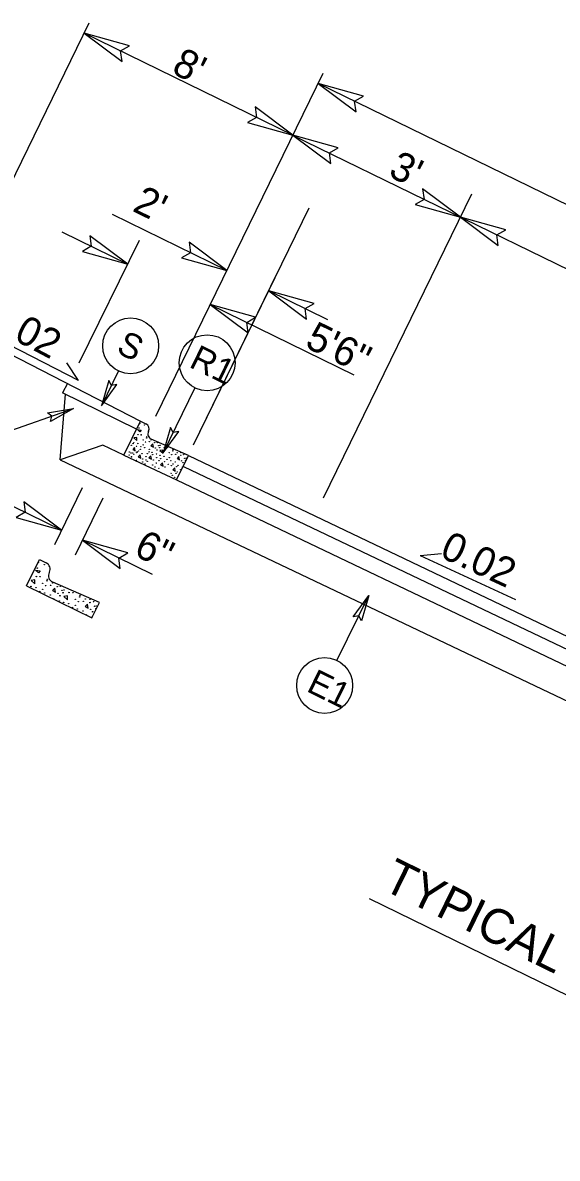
# Model space of a CAD drawing. Extents: x 1518247 to 1523638, y 635234 to 639927.
# Drawn here: x 1522742.5 to 1522926, y 636882.6 to 637272.1 of the extents above; entities that cross this region are included whole.
import ezdxf

# ---------------------------------------------------------------- set-up
doc = ezdxf.new("R2010")
doc.units = 0
for name, color, linetype in [('Prop Dimension', 7, 'Continuous'), ('Prop Dimension Text', 7, 'Continuous'), ('Prop Shade Light', 7, 'Continuous'), ('Typical Arrow Superelevation CELL', 7, 'Continuous'), ('Typical Berm CELL', 7, 'Continuous'), ('Typical Berm Information CELL', 7, 'Continuous'), ('Typical Curb CELL', 7, 'Continuous'), ('Typical Hinge Slope Interstate CELL', 7, 'Continuous'), ('Typical ID Circle CELL', 7, 'Continuous'), ('Typical Pavement Slope CELL', 7, 'Continuous'), ('Typical Pavement Slope Information CELL', 7, 'Continuous'), ('Typical Text ID Circle CELL', 7, 'Continuous'), ('Typical Text Label CELL', 7, 'Continuous')]:
    doc.layers.add(name, color=color, linetype=linetype)

# ---------------------------------------------------------------- blocks, each defined once
blk = doc.blocks.new('TERMINATOR')
at = {"layer": 'Prop Shade Light'}
blk.add_lwpolyline([(-0.469, 0.081), (0, 0), (-0.471, -0.083), (-0.411, 0)], close=True, dxfattribs=at)

msp = doc.modelspace()

# ---------------------------------------------------------------- linework, layer by layer
at = {"layer": 'Prop Dimension'}
for p, q in [((1522717.34, 637173.63), (1522765.38, 637272.05)), ((1522835.27, 637233.49), (1522763.63, 637268.47)), ((1522788.25, 637137.16), (1522845.66, 637254.76)), ((1523261.87, 637047.19), (1522843.93, 637251.22)), ((1523044.19, 637131.41), (1522835.23, 637233.41)), ((1522845.74, 637109.11), (1522896.65, 637213.41)), ((1522801.16, 637127.25), (1522840.88, 637208.62)), ((1522812.62, 637187.09), (1522773.32, 637206.27)), ((1522755.94, 637200.38), (1522778.55, 637189.3)), ((1522761.93, 637155.39), (1522782.56, 637197.49)), ((1522801.16, 637127.26), (1522829.89, 637186.12)), ((1522847.25, 637170.18), (1522826.95, 637180.09)), ((1522806.91, 637175.4), (1522856.1, 637151.3)), ((1522755.85, 637098.06), (1522727.21, 637112.05)), ((1522762.91, 637112.52), (1522753.38, 637093)), ((1522770.07, 637109.03), (1522760.54, 637089.5)), ((1522787.02, 637082.85), (1522763.01, 637094.56))]:
    msp.add_line(p, q, dxfattribs=at)
at = {"layer": 'Prop Shade Light'}
for points in [[(1522772.04, 637149.31), (1522769.52, 637140.66), (1522774.85, 637147.99), (1522772.94, 637147.66)], [(1522751.04, 637138.26), (1522759.92, 637139.77), (1522752.03, 637135.32), (1522752.57, 637137.18)], [(1522793.25, 637133.22), (1522790.73, 637124.58), (1522796.07, 637131.91), (1522794.15, 637131.58)], [(1522855.97, 637068.32), (1522861.25, 637075.62), (1522858.74, 637066.91), (1522857.82, 637068.62)]]:
    msp.add_lwpolyline(points, close=True, dxfattribs=at)
at = {"layer": 'Typical Arrow Superelevation CELL'}
msp.add_line((1522761.64, 637149.3), (1522757.69, 637155.44), dxfattribs=at)
at = {"layer": 'Typical Berm CELL'}
for p, q in [((1522715.59, 637170.05), (1522782.95, 637135.4)), ((1522781.6, 637132.64), (1522756.23, 637145.14))]:
    msp.add_line(p, q, dxfattribs=at)
at = {"layer": 'Typical Berm Information CELL'}
msp.add_line((1522761.64, 637149.3), (1522727.1, 637167.06), dxfattribs=at)
at = {"layer": 'Typical Curb CELL'}
for p, q in [((1522777.24, 637123.7), (1522782.95, 637135.4)), ((1522782.95, 637135.4), (1522784.82, 637134.49)), ((1522781.68, 637129.84), (1522780.68, 637129.66)), ((1522780.68, 637129.66), (1522781.72, 637128.8)), ((1522781.72, 637128.8), (1522781.68, 637129.84)), ((1522782.71, 637131.76), (1522781.89, 637132.57)), ((1522781.89, 637132.57), (1522783.15, 637132.35)), ((1522783.15, 637132.35), (1522782.71, 637131.76)), ((1522785.66, 637131.86), (1522785.7, 637131.94)), ((1522799.41, 637123.67), (1522786.61, 637129.27)), ((1522780.93, 637126.38), (1522780.28, 637125.69)), ((1522780.28, 637125.69), (1522781.13, 637125.22)), ((1522781.13, 637125.22), (1522780.93, 637126.38)), ((1522787.19, 637127.65), (1522786.54, 637126.96)), ((1522786.54, 637126.96), (1522787.38, 637126.49)), ((1522787.38, 637126.49), (1522787.19, 637127.65)), ((1522790.63, 637125.47), (1522789.63, 637125.3)), ((1522789.63, 637125.3), (1522790.67, 637124.43)), ((1522790.67, 637124.43), (1522790.63, 637125.47)), ((1522777.24, 637123.7), (1522795.32, 637115.31)), ((1522782.82, 637123.87), (1522782.18, 637123.18)), ((1522782.18, 637123.18), (1522783.02, 637122.71)), ((1522783.02, 637122.71), (1522782.82, 637123.87)), ((1522786.49, 637123.54), (1522785.85, 637122.85)), ((1522785.85, 637122.85), (1522786.69, 637122.38)), ((1522786.69, 637122.38), (1522786.49, 637123.54)), ((1522790.49, 637121.17), (1522789.85, 637120.48)), ((1522790.69, 637120.01), (1522790.49, 637121.17)), ((1522795.32, 637115.31), (1522799.41, 637123.67)), ((1522796.14, 637123.28), (1522795.49, 637122.59)), ((1522795.49, 637122.59), (1522796.34, 637122.12)), ((1522796.34, 637122.12), (1522796.14, 637123.28)), ((1522789.85, 637120.48), (1522790.69, 637120.01)), ((1522794.7, 637119.41), (1522794.06, 637118.71)), ((1522794.06, 637118.71), (1522794.9, 637118.24)), ((1522794.9, 637118.24), (1522794.7, 637119.41)), ((1522743.84, 637078.94), (1522748.24, 637087.92)), ((1522748.24, 637087.92), (1522750.58, 637086.78)), ((1522747.94, 637083.35), (1522746.9, 637084.37)), ((1522746.9, 637084.37), (1522748.49, 637084.09)), ((1522748.49, 637084.09), (1522747.94, 637083.35)), ((1522751.63, 637083.48), (1522751.68, 637083.57)), ((1522743.84, 637078.94), (1522766.3, 637067.96)), ((1522746.64, 637080.95), (1522745.38, 637080.73)), ((1522745.38, 637080.73), (1522746.69, 637079.65)), ((1522746.69, 637079.65), (1522746.64, 637080.95)), ((1522753.54, 637078.2), (1522752.74, 637077.33)), ((1522768.86, 637073.2), (1522752.82, 637080.23)), ((1522753.79, 637076.75), (1522753.54, 637078.2)), ((1522752.74, 637077.33), (1522753.79, 637076.75)), ((1522757.85, 637075.46), (1522756.6, 637075.24)), ((1522756.6, 637075.24), (1522757.91, 637074.16)), ((1522757.91, 637074.16), (1522757.85, 637075.46)), ((1522764.76, 637072.71), (1522763.95, 637071.84)), ((1522763.95, 637071.84), (1522765.01, 637071.25)), ((1522765.01, 637071.25), (1522764.76, 637072.71)), ((1522766.3, 637067.96), (1522768.86, 637073.2))]:
    msp.add_line(p, q, dxfattribs=at)
for centre, radius in [((1522782.39, 637133.08), 0.064), ((1522782.66, 637134.57), 0.064), ((1522784.34, 637134.05), 0.064), ((1522782.13, 637130.78), 0.064), ((1522783.17, 637130.72), 0.064), ((1522783.86, 637128.93), 0.064), ((1522785.05, 637129.61), 0.064), ((1522785.11, 637130.03), 0.064), ((1522786.58, 637129.01), 0.064), ((1522779.09, 637124.85), 0.064), ((1522779.76, 637127.1), 0.064), ((1522780.33, 637127.73), 0.064), ((1522780.65, 637128.06), 0.064), ((1522781.58, 637126.77), 0.064), ((1522781.78, 637124.9), 0.064), ((1522782.02, 637127.75), 0.064), ((1522782.22, 637125.23), 0.064), ((1522782.91, 637125.77), 0.064), ((1522783.07, 637126.68), 0.064), ((1522783.88, 637127.3), 0.064), ((1522784.39, 637126.28), 0.064), ((1522784.66, 637128.28), 0.064), ((1522785.89, 637124.9), 0.064), ((1522785.95, 637125.73), 0.064), ((1522786.02, 637128.38), 0.064), ((1522787.84, 637128.05), 0.064), ((1522788.04, 637126.18), 0.064), ((1522788.57, 637125.51), 0.064), ((1522788.68, 637128.01), 0.064), ((1522789.17, 637127.04), 0.064), ((1522789.48, 637126.34), 0.064), ((1522789.69, 637127.09), 0.064), ((1522791.08, 637126.41), 0.064), ((1522792.12, 637126.35), 0.064), ((1522794.01, 637125.24), 0.064), ((1522794.06, 637125.66), 0.064), ((1522779.06, 637123.82), 0.064), ((1522779.69, 637124.46), 0.064), ((1522779.86, 637123.18), 0.064), ((1522780.25, 637124.51), 0.064), ((1522780.66, 637124.07), 0.064), ((1522781.58, 637121.95), 0.064), ((1522781.66, 637124.6), 0.064), ((1522783.48, 637124.27), 0.064), ((1522783.65, 637121.38), 0.064), ((1522783.68, 637122.4), 0.064), ((1522784.81, 637123.26), 0.064), ((1522784.84, 637122.06), 0.064), ((1522785.25, 637121.62), 0.064), ((1522785.33, 637124.27), 0.064), ((1522786.85, 637124.68), 0.064), ((1522787.14, 637123.94), 0.064), ((1522787.34, 637122.07), 0.064), ((1522788.33, 637121.02), 0.064), ((1522788.44, 637124.11), 0.064), ((1522788.47, 637122.93), 0.064), ((1522789.33, 637121.9), 0.064), ((1522789.6, 637123.69), 0.064), ((1522789.89, 637122.53), 0.064), ((1522790.97, 637123.38), 0.064), ((1522791.14, 637121.57), 0.064), ((1522792.02, 637122.31), 0.064), ((1522792.81, 637124.56), 0.064), ((1522792.83, 637122.93), 0.064), ((1522793.35, 637121.91), 0.064), ((1522793.61, 637123.91), 0.064), ((1522794.9, 637121.36), 0.064), ((1522794.97, 637124.01), 0.064), ((1522795.53, 637124.64), 0.064), ((1522796.79, 637123.68), 0.064), ((1522796.82, 637124.57), 0.064), ((1522796.99, 637121.81), 0.064), ((1522797.52, 637121.14), 0.064), ((1522797.78, 637123.95), 0.064), ((1522798.12, 637122.67), 0.064), ((1522798.43, 637121.97), 0.064), ((1522798.64, 637122.72), 0.064), ((1522784.45, 637120.73), 0.064), ((1522787.13, 637120.34), 0.064), ((1522787.93, 637119.69), 0.064), ((1522789.25, 637119.25), 0.064), ((1522791.34, 637119.7), 0.064), ((1522792.48, 637120.56), 0.064), ((1522793.46, 637117.48), 0.064), ((1522793.54, 637120.13), 0.064), ((1522794.1, 637120.76), 0.064), ((1522795.1, 637117.51), 0.064), ((1522795.36, 637119.8), 0.064), ((1522795.56, 637117.93), 0.064), ((1522795.8, 637120.31), 0.064), ((1522796.69, 637118.8), 0.064), ((1522797.39, 637119.74), 0.064), ((1522793.9, 637116.83), 0.064), ((1522794.7, 637116.18), 0.064), ((1522747.87, 637086.87), 0.0802), ((1522749.97, 637086.23), 0.0802), ((1522747.21, 637082.13), 0.0802), ((1522747.53, 637085.01), 0.0802), ((1522748.51, 637082.06), 0.0802), ((1522745.35, 637078.72), 0.0802), ((1522747.06, 637078.32), 0.0802), ((1522749.37, 637079.8), 0.0802), ((1522750.37, 637078.99), 0.0802), ((1522750.87, 637080.66), 0.0802), ((1522750.94, 637081.18), 0.0802), ((1522752.08, 637079.11), 0.0802), ((1522752.79, 637079.9), 0.0802), ((1522754.36, 637078.69), 0.0802), ((1522755.47, 637078.75), 0.0802), ((1522748.37, 637076.98), 0.0802), ((1522749.39, 637077.76), 0.0802), ((1522750.04, 637076.49), 0.0802), ((1522751.98, 637075.79), 0.0802), ((1522753.12, 637074.47), 0.0802), ((1522754.61, 637076.35), 0.0802), ((1522755.27, 637075.52), 0.0802), ((1522756.03, 637077.43), 0.0802), ((1522756.41, 637076.55), 0.0802), ((1522756.68, 637077.49), 0.0802), ((1522758.43, 637076.64), 0.0802), ((1522759.73, 637076.57), 0.0802), ((1522760.59, 637074.31), 0.0802), ((1522762.09, 637075.17), 0.0802), ((1522762.16, 637075.7), 0.0802), ((1522764.01, 637074.41), 0.0802), ((1522765.62, 637074.32), 0.0802), ((1522755.11, 637073.75), 0.0802), ((1522756.57, 637073.23), 0.0802), ((1522758.28, 637072.84), 0.0802), ((1522759.59, 637071.5), 0.0802), ((1522760.61, 637072.27), 0.0802), ((1522761.26, 637071), 0.0802), ((1522761.59, 637073.5), 0.0802), ((1522763.21, 637070.3), 0.0802), ((1522763.3, 637073.62), 0.0802), ((1522765.58, 637073.21), 0.0802), ((1522765.83, 637070.86), 0.0802), ((1522766.82, 637073.54), 0.0802), ((1522767.25, 637071.95), 0.0802), ((1522767.63, 637071.06), 0.0802), ((1522767.9, 637072.01), 0.0802), ((1522764.34, 637068.98), 0.0802), ((1522766.33, 637068.26), 0.0802), ((1522766.49, 637070.03), 0.0802)]:
    msp.add_circle(centre, radius, dxfattribs=at)
for centre, radius, start, end in [((1522783.98, 637132.78), 1.91, 333.9793, 63.9793), ((1522787.38, 637131.02), 1.91, 153.9793, 246.3637), ((1522749.52, 637084.63), 2.4, 333.9377, 63.9377), ((1522753.78, 637082.43), 2.4, 153.9377, 246.3222)]:
    msp.add_arc(centre, radius, start, end, dxfattribs=at)
at = {"layer": 'Typical Hinge Slope Interstate CELL'}
msp.add_line((1522757.86, 637148.3), (1522756.23, 637145.14), dxfattribs=at)
at = {"layer": 'Typical ID Circle CELL'}
for p, q in [((1522775.36, 637152.62), (1522769.52, 637140.66)), ((1522801.6, 637146.84), (1522790.73, 637124.58)), ((1522736.55, 637131.53), (1522759.92, 637139.77)), ((1522850.35, 637053.37), (1522861.25, 637075.62))]:
    msp.add_line(p, q, dxfattribs=at)
for centre in [(1522779.56, 637161.23), (1522805.81, 637155.45), (1522846.13, 637044.76)]:
    msp.add_circle(centre, 9.59, dxfattribs=at)
at = {"layer": 'Typical Pavement Slope CELL'}
for p, q in [((1522755.34, 637122.13), (1522757.24, 637144.64)), ((1522770.07, 637127.19), (1522755.34, 637122.13)), ((1522777.24, 637123.7), (1522770.07, 637127.19)), ((1522755.34, 637122.13), (1522986.45, 637012.21)), ((1522799.41, 637123.67), (1522994.84, 637030.3)), ((1522797.66, 637119.84), (1522993.16, 637026.68)), ((1522795.32, 637115.31), (1522990.92, 637021.86))]:
    msp.add_line(p, q, dxfattribs=at)
at = {"layer": 'Typical Pavement Slope Information CELL'}
for q in [(1522886.19, 637090.01), (1522911.58, 637074.21)]:
    msp.add_line((1522878.93, 637089.35), q, dxfattribs=at)
at = {"layer": 'Typical Text Label CELL'}
msp.add_line((1522861.46, 636971.76), (1523043.36, 636882.64), dxfattribs=at)

# ---------------------------------------------------------------- block references
at = {"layer": 'Prop Dimension', "xscale": 33.82820784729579, "yscale": -36.41552511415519}
for p, rotation in [((1522763.63, 637268.47), 153.97926941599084), ((1522843.93, 637251.22), 153.97926941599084), ((1522835.27, 637233.49), -26.020730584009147), ((1522835.27, 637233.49), 153.97926941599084), ((1522892.73, 637205.36), -26.020730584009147), ((1522892.73, 637205.36), 153.97926941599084), ((1522778.55, 637189.3), -26.020730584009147), ((1522812.62, 637187.09), -26.020730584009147), ((1522826.95, 637180.09), 153.97926941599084), ((1522806.91, 637175.4), 153.97926941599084), ((1522755.85, 637098.06), -26.020730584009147), ((1522763.01, 637094.56), 153.97926941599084)]:
    msp.add_blockref('TERMINATOR', p, dxfattribs=dict(at, rotation=rotation))

# ---------------------------------------------------------------- texts
at = {"layer": 'Prop Dimension'}
for s, p in [("8'", (1522793.22, 637254.95)), ("3'", (1522867.58, 637219.59)), ("2'", (1522779.79, 637207.63)), ('5\'6"', (1522838.95, 637161.01)), ('6"', (1522780.21, 637089.62))]:
    msp.add_text(s, height=9.969, rotation=333.9793, dxfattribs=at).set_placement(p)
at = {"layer": 'Prop Dimension Text'}
msp.add_text('TYPICAL SECTION NO. 2', height=11.9625, rotation=333.8962, dxfattribs=at).set_placement((1522865.42, 636975.1))
at = {"layer": 'Typical Berm Information CELL'}
msp.add_text('0.02', height=9.969, rotation=332.1708, dxfattribs=at).set_placement((1522729.3, 637168.63))
at = {"layer": 'Typical Pavement Slope Information CELL'}
msp.add_text('0.02', height=9.969, rotation=335.125, dxfattribs=at).set_placement((1522885.22, 637089.01))
at = {"layer": 'Typical Text ID Circle CELL'}
for s, height, rotation, p in [('S', 8.58, 333.9793, (1522774.28, 637159.08)), ('R1', 8.581, 333.9793, (1522799.27, 637154.14)), ('E1', 8.581, 333.8962, (1522839.53, 637042.95))]:
    msp.add_text(s, height=height, rotation=rotation, dxfattribs=at).set_placement(p)

doc.saveas('drawing.dxf')
